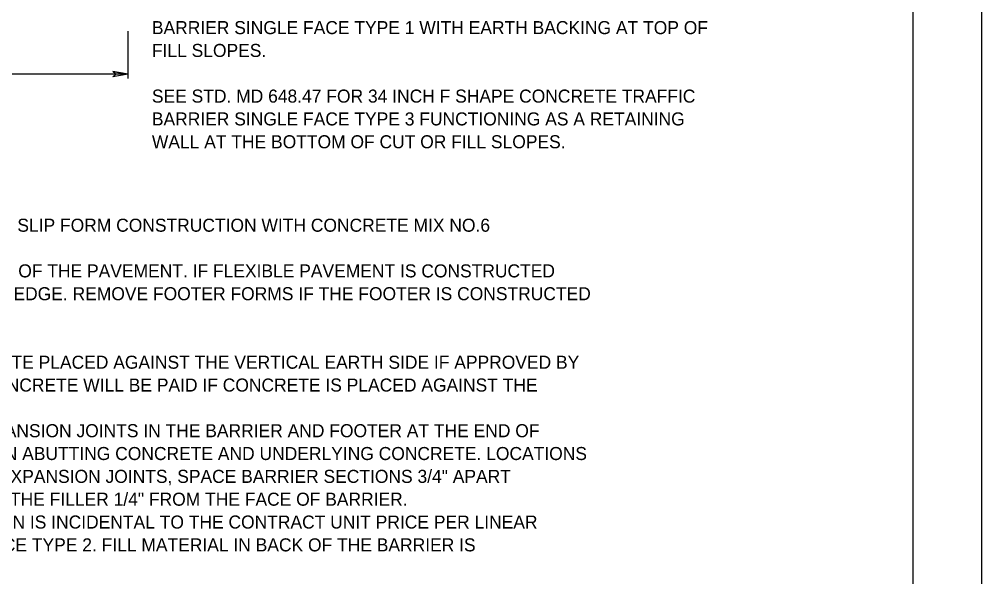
# Model space of a CAD drawing. Extents: x -32.9 to -15.8, y -6.5 to 4.5.
# Drawn here: x -20.254 to -15.824, y -3.933 to -1.368 of the extents above; entities that cross this region are included whole.
import ezdxf

# ---------------------------------------------------------------- set-up
doc = ezdxf.new("R2010")
doc.units = 0
for name, color, linetype in [('BORD-LINE', 7, 'Continuous'), ('DETL-DIMS', 7, 'Continuous'), ('Level 10', 7, 'Continuous'), ('Level 12', 7, 'Continuous'), ('Level 13', 7, 'Continuous'), ('USER-CLIP', 7, 'Continuous')]:
    doc.layers.add(name, color=color, linetype=linetype)

msp = doc.modelspace()

# ---------------------------------------------------------------- linework, layer by layer
at = {"layer": 'BORD-LINE'}
msp.add_lwpolyline([(-23.5151, 4.1733), (-16.1409, 4.1733), (-16.1409, -6.1798), (-23.5151, -6.1798)], close=True, dxfattribs=at)
at = {"layer": 'DETL-DIMS'}
for p, q in [((-19.752, -1.6207), (-19.8236, -1.6334)), ((-19.81, -1.6207), (-19.8236, -1.6334)), ((-19.752, -1.6207), (-19.8235, -1.6082)), ((-19.8235, -1.6082), (-19.81, -1.6207))]:
    msp.add_line(p, q, dxfattribs=at)
msp.add_lwpolyline([(-19.8235, -1.6082), (-19.752, -1.6207), (-19.8236, -1.6334), (-19.81, -1.6207)], close=True, dxfattribs=at)
at = {"layer": 'Level 10'}
for p, q in [((-19.752, -1.6415), (-19.752, -1.4234)), ((-19.752, -1.6207), (-22.0848, -1.6207))]:
    msp.add_line(p, q, dxfattribs=at)
at = {"layer": 'USER-CLIP'}
msp.add_lwpolyline([(-15.824, 4.5033), (-24.324, 4.5033), (-24.324, -6.4967), (-15.824, -6.4967)], close=True, dxfattribs=at)

# ---------------------------------------------------------------- texts
at = {"layer": 'Level 12'}
for s, p in [('BARRIER SINGLE FACE TYPE 1 WITH EARTH BACKING AT TOP OF ', (-19.6434, -1.4368)), ('FILL SLOPES.', (-19.6434, -1.5418)), ('SEE STD. MD 648.47 FOR 34 INCH F SHAPE CONCRETE TRAFFIC ', (-19.6434, -1.7518)), ('BARRIER SINGLE FACE TYPE 3 FUNCTIONING AS A RETAINING ', (-19.6434, -1.8568)), ('WALL AT THE BOTTOM OF CUT OR FILL SLOPES.', (-19.6434, -1.9618))]:
    msp.add_text(s, height=0.06001, dxfattribs=at).set_placement(p)
at = {"layer": 'Level 13'}
for s, p in [('CAST THE BARRIER AND FOOTER SEPARATELY USING FIXED FORM OR SLIP FORM CONSTRUCTION WITH CONCRETE MIX NO.6 ', (-23.0939, -2.3457)), ('THE BARRIER FOOTER MAY BE CONSTRUCTED AFTER CONSTRUCTION OF THE PAVEMENT. IF FLEXIBLE PAVEMENT IS CONSTRUCTED ', (-23.0939, -2.5557)), ('BEFORE THE FOOTER, SAWCUT THE PAVEMENT TO PROVIDE A CLEAN EDGE. REMOVE FOOTER FORMS IF THE FOOTER IS CONSTRUCTED ', (-23.0939, -2.6607)), ('THE FOOTER REAR VERTICAL FACE MAY BE FORMED OR THE CONCRETE PLACED AGAINST THE VERTICAL EARTH SIDE IF APPROVED BY ', (-23.0939, -2.9758)), ('THE ENGINEER. NO ADDITIONAL COMPENSATION FOR ADDITIONAL CONCRETE WILL BE PAID IF CONCRETE IS PLACED AGAINST THE ', (-23.0939, -3.0808)), ('MAXIMUM SPACING OF CONTRACTION JOINTS IS 20 FEET.  PLACE EXPANSION JOINTS IN THE BARRIER AND FOOTER AT THE END OF ', (-23.0939, -3.2908)), ('POUR. AT PC AND PT LOCATIONS, STRUCTURES, EXPANSION JOINTS IN ABUTTING CONCRETE AND UNDERLYING CONCRETE. LOCATIONS ', (-23.0939, -3.3958)), ('AS SHOWN ON THE PLANS, AND AS DIRECTED BY THE ENGINEER. AT EXPANSION JOINTS, SPACE BARRIER SECTIONS 3/4" APART', (-23.0939, -3.5009)), ('AND FILL THE OPENING WITH 3/4" PREFORMED JOINT FILLER. RECESS THE FILLER 1/4" FROM THE FACE OF BARRIER.', (-23.0939, -3.6059)), ('COST OF THE CONCRETE FOOTER, REINFORCEMENT, AND EXCAVATION IS INCIDENTAL TO THE CONTRACT UNIT PRICE PER LINEAR ', (-23.0939, -3.7109)), ('FOOT FOR 34 INCH F SHAPE CONCRETE TRAFFIC BARRIER SINGLE FACE TYPE 2. FILL MATERIAL IN BACK OF THE BARRIER IS ', (-23.0939, -3.8159))]:
    msp.add_text(s, height=0.0600095, dxfattribs=at).set_placement(p)

doc.saveas('drawing.dxf')
